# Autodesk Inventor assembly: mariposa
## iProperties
Shininess: 64.0
Length Units: 11272
Angle Units: 11279
Time Units: 11290
Mass Units: 11286
Length Display Precision: 3
Angle Display Precision: 2
Compacted: True
Part Number: mariposa
Document SubType Name: Assembly
Created: 2005-06
Designer: alek
Manufacturer: Standard
Standards Organization: Custom
Density: 0.0
Volumn: 0.0
Area: 0.0
PropertySet Name: Model Information
Control State: 0
Master: False
Checked Out: False
Author: alek
